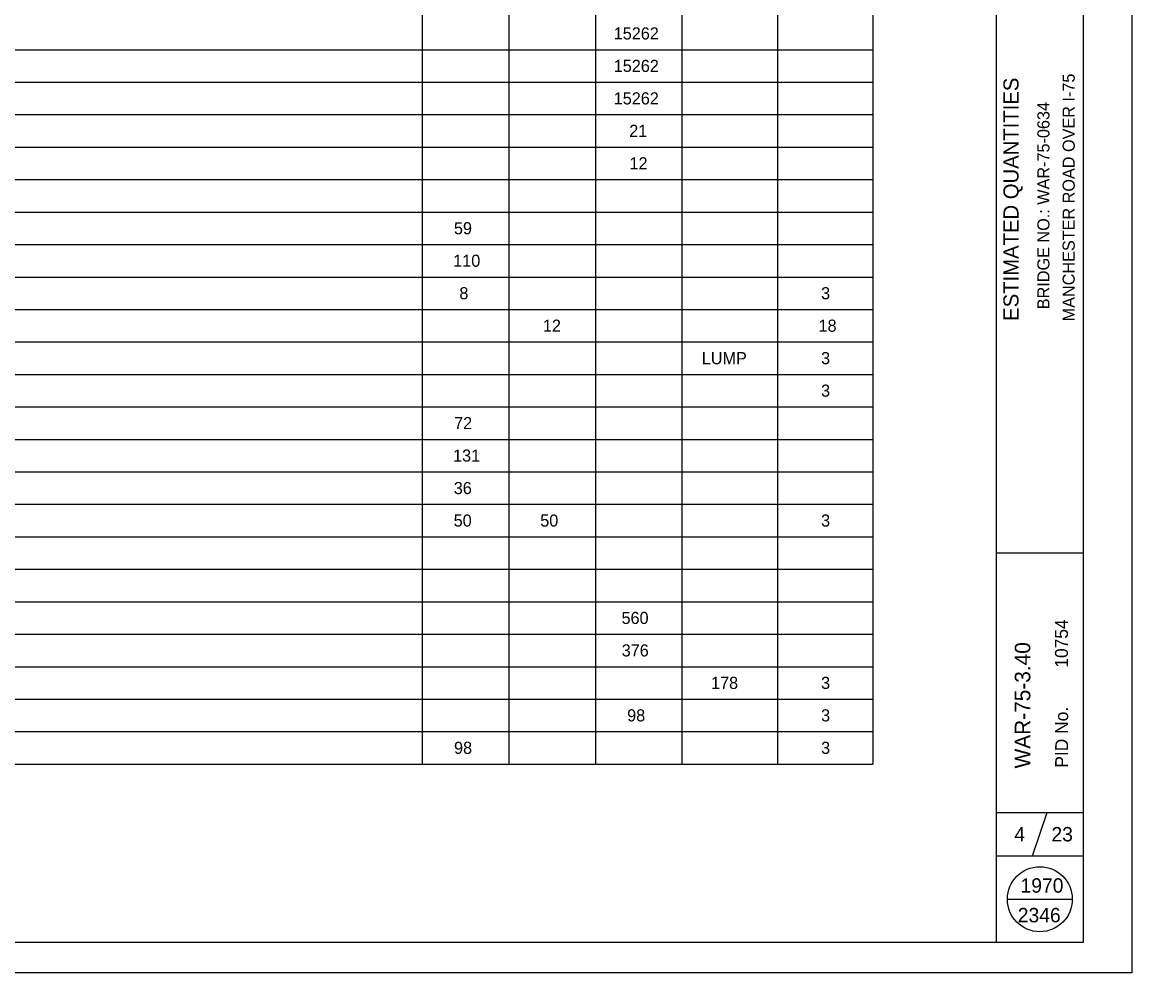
# Model space of a CAD drawing. Extents: x -70.8 to -34.9, y -11.1 to 10.9.
# Drawn here: x -48.33 to -35.51, y -10.99 to -0.02 of the extents above; entities that cross this region are included whole.
import ezdxf

# ---------------------------------------------------------------- set-up
doc = ezdxf.new("R2010")
doc.units = 0
for name, color, linetype in [('BR_P_Gen_Ground_Slope', 7, 'Continuous'), ('BR_P_Gen_Text', 7, 'Continuous'), ('SH_Border', 7, 'Continuous'), ('SH_Cut_Line', 7, 'Continuous'), ('SH_Data', 7, 'Continuous')]:
    doc.layers.add(name, color=color, linetype=linetype)

msp = doc.modelspace()

# ---------------------------------------------------------------- linework, layer by layer
at = {"layer": 'BR_P_Gen_Ground_Slope'}
for p, q in [((-38.5, 7.824), (-38.5, -8.584)), ((-43.705, 7.166), (-43.705, -8.584)), ((-42.705, 7.166), (-42.705, -8.584)), ((-41.705, 7.166), (-41.705, -8.584)), ((-40.705, 7.166), (-40.705, -8.584)), ((-39.603, 7.166), (-39.603, -8.584)), ((-66.205, -0.334), (-38.5, -0.334)), ((-66.205, -0.709), (-38.5, -0.709)), ((-66.205, -1.084), (-38.5, -1.084)), ((-66.205, -1.459), (-38.5, -1.459)), ((-66.205, -1.834), (-38.5, -1.834)), ((-66.205, -2.209), (-38.5, -2.209)), ((-66.205, -2.584), (-38.5, -2.584)), ((-66.205, -2.959), (-38.5, -2.959)), ((-66.205, -3.334), (-38.5, -3.334)), ((-66.205, -3.709), (-38.5, -3.709)), ((-66.205, -4.084), (-38.5, -4.084)), ((-66.205, -4.459), (-38.5, -4.459)), ((-66.205, -4.834), (-38.5, -4.834)), ((-66.205, -5.209), (-38.5, -5.209)), ((-66.205, -5.584), (-38.5, -5.584)), ((-66.205, -5.959), (-38.5, -5.959)), ((-66.205, -6.334), (-38.5, -6.334)), ((-66.205, -6.709), (-38.5, -6.709)), ((-66.205, -7.084), (-38.5, -7.084)), ((-66.205, -7.459), (-38.5, -7.459)), ((-66.205, -7.834), (-38.5, -7.834)), ((-66.205, -8.209), (-38.5, -8.209)), ((-66.205, -8.584), (-38.5, -8.584))]:
    msp.add_line(p, q, dxfattribs=at)
at = {"layer": 'SH_Border'}
for p, q in [((-37.071, -10.644), (-37.071, 10.356)), ((-37.071, -6.144), (-36.071, -6.144)), ((-37.071, -9.144), (-36.071, -9.144)), ((-36.655, -9.644), (-36.488, -9.144)), ((-37.071, -9.644), (-36.071, -9.644))]:
    msp.add_line(p, q, dxfattribs=at)
msp.add_lwpolyline([(-67.571, 10.356), (-36.071, 10.356), (-36.071, -10.644), (-67.571, -10.644)], close=True, dxfattribs=at)
at = {"layer": 'SH_Cut_Line'}
msp.add_lwpolyline([(-35.509, -10.994), (-69.509, -10.994), (-69.509, 10.656), (-35.509, 10.656)], close=True, dxfattribs=at)
at = {"layer": 'SH_Data'}
msp.add_line((-36.946, -10.144), (-36.196, -10.144), dxfattribs=at)
msp.add_circle((-36.571, -10.144), 0.375, dxfattribs=at)

# ---------------------------------------------------------------- texts
at = {"layer": 'BR_P_Gen_Text'}
for s, p in [('15262', (-41.493, -0.216)), ('15262', (-41.493, -0.591)), ('15262', (-41.493, -0.966)), ('21', (-41.314, -1.341)), ('12', (-41.311, -1.716)), ('59', (-43.339, -2.466)), ('110', (-43.347, -2.841)), ('8', (-43.276, -3.216)), ('3', (-39.098, -3.216)), ('12', (-42.311, -3.591)), ('18', (-39.127, -3.591)), ('LUMP', (-40.476, -3.966)), ('3', (-39.098, -3.966)), ('3', (-39.098, -4.341)), ('72', (-43.337, -4.716)), ('131', (-43.349, -5.091)), ('36', (-43.341, -5.466)), ('50', (-43.342, -5.841)), ('50', (-42.342, -5.841)), ('3', (-39.098, -5.841)), ('560', (-41.403, -6.966)), ('376', (-41.401, -7.341)), ('178', (-40.369, -7.716)), ('3', (-39.098, -7.716)), ('98', (-41.338, -8.091)), ('3', (-39.098, -8.091)), ('98', (-43.338, -8.466)), ('3', (-39.098, -8.466))]:
    msp.add_text(s, height=0.14, dxfattribs=at).set_placement(p)
at = {"layer": 'SH_Data'}
for s, height, p in [('MANCHESTER ROAD OVER I-75', 0.14, (-36.168, -3.471)), ('ESTIMATED QUANTITIES', 0.175, (-36.817, -3.465)), ('BRIDGE NO.: WAR-75-0634', 0.14, (-36.46, -3.331)), (' 10754', 0.15, (-36.246, -7.526)), ('WAR-75-3.40', 0.18, (-36.681, -8.634)), ('PID No.', 0.15, (-36.244, -8.625))]:
    msp.add_text(s, height=height, rotation=90, dxfattribs=at).set_placement(p)
for s, height, p in [('4', 0.167, (-36.866, -9.477)), ('23', 0.1666, (-36.437, -9.477)), ('1970', 0.1666, (-36.794, -10.069)), ('2346', 0.1666, (-36.826, -10.411))]:
    msp.add_text(s, height=height, dxfattribs=at).set_placement(p)

doc.saveas('drawing.dxf')
